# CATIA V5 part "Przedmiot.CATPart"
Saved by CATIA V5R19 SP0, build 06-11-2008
Bounding box of the stored display mesh (mm): x -53.89 to 96.11, y -51.206 to 48.794, z 0 to 30
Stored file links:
  G:\Catia\CD\NarozaPrzejscia\Przedmiot.CATPart
  D:\POBO\CATIA Tutorials\Machining modules\PMG_F\Student\Data\DesignPart.CATPart
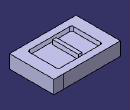
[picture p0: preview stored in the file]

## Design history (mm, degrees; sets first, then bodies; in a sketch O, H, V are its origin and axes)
Body1 "Przedmiot" (main body)
  Sketch1 on xy-plane, origin (0, 0, 0), H (1, 0, 0), V (0, 1, 0)
    point P1 (-53.8903, 48.7944)
    line L1 (-53.8903, 48.7944) -> (73.6097, 48.7944)
    line L2 (73.6097, -51.2056) -> (-53.8903, -51.2056)
    line L3 (-53.8903, -51.2056) -> (-53.8903, 48.7944)
    point P2 (96.1097, 48.7944)
    point P3 (96.1097, -51.2056)
    line L4 (73.6097, 48.7944) -> (96.1097, 48.7944)
    line L5 (73.6097, -51.2056) -> (96.1097, -51.2056)
    line L6 (96.1097, 48.7944) -> (96.1097, -51.2056)
    distance P2 P3 = 100
    distance P1 P2 = 150
    horizontal: L1 H, L2 H, L4 H, L5 H
    vertical: L3 V, L6 V
  Pad1: profile Sketch1, direction (0, 0, 1), length 30
  Sketch2 on end face of Pad1, origin (0, 0, 30), H (1, 0, 0), V (0, 1, 0)
    line L1 (-28.8903, 33.7944) -> (71.1097, 33.7944)
    line L2 (71.1097, 33.7944) -> (71.1097, -36.2056)
    line L3 (71.1097, -36.2056) -> (-28.8903, -36.2056)
    line L4 (-28.8903, -36.2056) -> (-28.8903, 33.7944)
    reference projected line E1 (-53.8903, 54.9661) -> (-53.8903, -45.0339) from edge [face of Pad1 from Sketch1.L3 | end face of Pad1]
    reference projected line E2 (94.4241, 48.7944) -> (-55.5759, 48.7944) from edge [face of Pad1 from Sketch1.L1 | end face of Pad1]
    length L1 = 100
    distance L4 E1 = 25
    length L2 = 70
    distance L1 E2 = 15
    horizontal: L1 H, L3 H
    vertical: L2 V, L4 V
  Pocket1: profile Sketch2, direction (0, 0, -1), length 10
  Fillet1: radius 5, on edge [face of Pocket1 from Sketch2.L2 | face of Pocket1 from Sketch2.L3]
  Fillet2: radius 5, on edge [face of Pocket1 from Sketch2.L1 | face of Pocket1 from Sketch2.L2]; edge [face of Pocket1 from Sketch2.L4 | face of Pocket1 from Sketch2.L1]; edge [face of Pocket1 from Sketch2.L3 | face of Pocket1 from Sketch2.L4]
  Sketch3 on end face of Pocket1, origin (0, 0, 20), H (1, 0, 0), V (0, 1, 0)
    line L1 (11.9896, 27.7944) -> (19.8951, 27.7944)
    line L2 (19.8951, 27.7944) -> (19.8951, -30.2056)
    line L3 (19.8951, -30.2056) -> (11.9896, -30.2056)
    line L4 (11.9896, -30.2056) -> (11.9896, 27.7944)
    reference projected line E1 (71.1097, 33.7944) -> (-28.8903, 33.7944) from edge [end face of Pad1 | face of Pocket1 from Sketch2.L1]
    length L2 = 58
    distance L1 E1 = 6
    horizontal: L1 H, L3 H
    vertical: L2 V, L4 V
  Pad2: profile Sketch3, direction (0, 0, 1), length 10
Body2 "Polfabrykat"
  Sketch4 on xy-plane, origin (0, 0, 0), H (1, 0, 0), V (0, 1, 0)
    construction line L1 through (0, 0) direction (1, 0)
    line L2 (-53.8903, 48.7944) -> (73.6097, 48.7944)
    line L3 (73.6097, -51.2056) -> (-53.8903, -51.2056)
    construction line L4 through (0, 0) direction (0, 1)
    line L5 (-53.8903, -51.2056) -> (-53.8903, 48.7944)
    point P1 (96.1097, -51.2056)
    point P2 (96.1097, 48.7944)
    line L6 (73.6097, 48.7944) -> (96.1097, 48.7944)
    line L7 (73.6097, -51.2056) -> (96.1097, -51.2056)
    line L8 (96.1097, 48.7944) -> (96.1097, -51.2056)
    point P3 (0, 0)
    distance P2 P1 = 100
    horizontal: L2 L1, L3 L1, L6 L1, L7 L1
    vertical: L5 L4, L8 L4
  Pad3: profile Sketch4, direction (0, 0, 1), length 30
